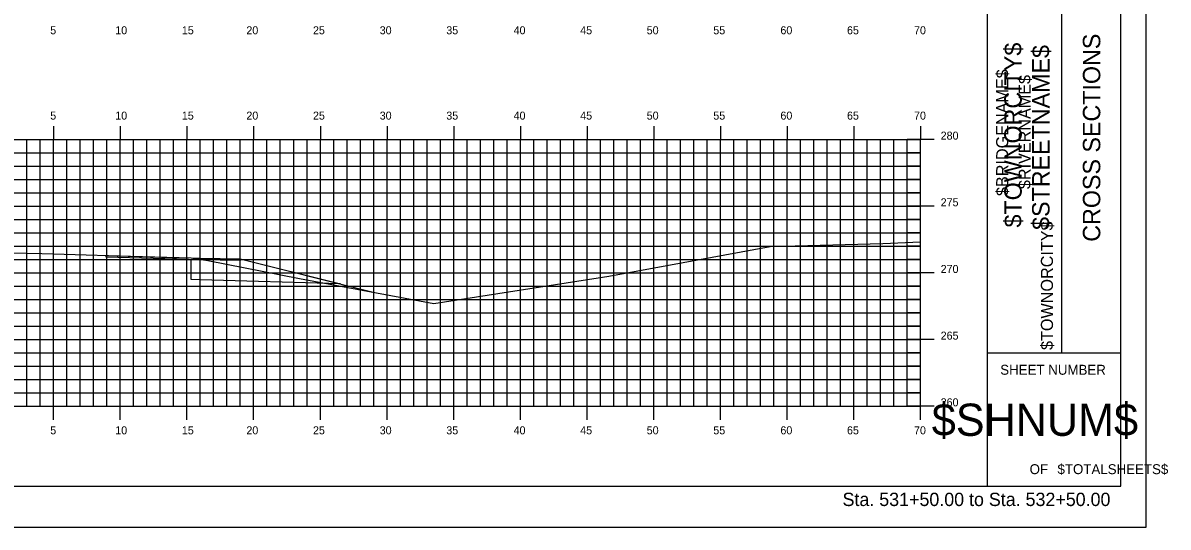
# Model space of a CAD drawing. Extents: x 1168600 to 1177589, y 610178 to 611246.
# Drawn here: x 1176838.4 to 1176924.2, y 610268.7 to 610306.6 of the extents above; entities that cross this region are included whole.
import ezdxf

# ---------------------------------------------------------------- set-up
doc = ezdxf.new("R2010")
doc.units = 0
for name, color, linetype in [('_Construction', 7, 'Continuous'), ('_Station Equation', 7, 'Continuous'), ('D_Roadway_Edge_TW', 7, 'Continuous'), ('D_Roadway_SubGrade', 7, 'Continuous'), ('D_Slope_Direction', 7, 'Continuous'), ('D_Text_Standard', 7, 'Continuous'), ('H_V ANNOTATION', 7, 'Continuous'), ('MAJOR', 7, 'Continuous'), ('MATCH LINES', 7, 'Continuous'), ('MINOR', 7, 'Continuous')]:
    doc.layers.add(name, color=color, linetype=linetype)

msp = doc.modelspace()

# ---------------------------------------------------------------- linework, layer by layer
at = {"layer": '_Construction'}
for p, q in [((1176910.655, 610271.804), (1176910.655, 610376.804)), ((1176920.655, 610271.804), (1176920.655, 610376.804)), ((1176916.246, 610281.804), (1176916.246, 610316.804)), ((1176910.655, 610281.804), (1176920.655, 610281.804)), ((1176760.655, 610271.801), (1176920.655, 610271.801))]:
    msp.add_line(p, q, dxfattribs=at)
msp.add_lwpolyline([(1176752.561, 610268.742), (1176922.561, 610268.742), (1176922.561, 610378.742), (1176752.561, 610378.742)], close=True, dxfattribs=at)
at = {"layer": '_Station Equation'}
msp.add_lwpolyline([(1176837.564, 610289.309), (1176839.769, 610289.258), (1176848.1, 610289.014), (1176849.945, 610288.956), (1176850.97, 610288.929), (1176851.322, 610288.87), (1176851.415, 610288.849), (1176852.211, 610288.745), (1176859.099, 610287.386), (1176869.173, 610285.511), (1176882.278, 610287.566), (1176894.366, 610289.791), (1176902.811, 610290.009), (1176905.654, 610290.135)], dxfattribs=at)
at = {"layer": 'D_Roadway_Edge_TW'}
msp.add_lwpolyline([(1176844.604, 610289.116), (1176850.97, 610288.929), (1176851.655, 610288.909), (1176851.655, 610288.784), (1176844.604, 610288.991), (1176844.604, 610289.116)], dxfattribs=at)
msp.add_lwpolyline([(1176844.604, 610289.116), (1176850.97, 610288.929), (1176851.655, 610288.909), (1176851.655, 610288.784), (1176844.604, 610288.991), (1176844.604, 610289.116)], dxfattribs=at)
msp.add_lwpolyline([(1176844.604, 610289.116), (1176850.97, 610288.929), (1176851.655, 610288.909), (1176854.653, 610288.851), (1176854.653, 610288.726), (1176851.655, 610288.784), (1176844.604, 610288.991)], close=True, dxfattribs=at)
msp.add_lwpolyline([(1176844.604, 610289.116), (1176850.97, 610288.929), (1176851.655, 610288.909), (1176854.653, 610288.851), (1176854.653, 610288.726), (1176851.655, 610288.784), (1176844.604, 610288.991)], close=True, dxfattribs=at)
at = {"layer": 'D_Roadway_SubGrade'}
msp.add_lwpolyline([(1176851.655, 610288.909), (1176854.653, 610288.851), (1176862.157, 610286.975), (1176851.655, 610287.284), (1176850.97, 610287.304), (1176850.97, 610288.804), (1176851.655, 610288.784)], close=True, dxfattribs=at)
msp.add_lwpolyline([(1176851.655, 610288.909), (1176854.653, 610288.851), (1176862.157, 610286.975), (1176851.655, 610287.284), (1176850.97, 610287.304), (1176850.97, 610288.804), (1176851.655, 610288.784)], close=True, dxfattribs=at)
at = {"layer": 'D_Slope_Direction'}
msp.add_lwpolyline([(1176851.655, 610288.909), (1176854.653, 610288.851)], dxfattribs=at)
msp.add_lwpolyline([(1176851.655, 610288.909), (1176854.653, 610288.851)], dxfattribs=at)
at = {"layer": 'D_Text_Standard'}
msp.add_lwpolyline([(1176844.604, 610289.116), (1176849.572, 610288.97), (1176850.97, 610288.929), (1176851.491, 610288.914), (1176851.655, 610288.909), (1176854.11, 610288.861), (1176854.653, 610288.851), (1176864.024, 610286.508), (1176864.624, 610286.358)], dxfattribs=at)
at = {"layer": 'MAJOR'}
for p, q in [((1176840.654, 610298.803), (1176840.654, 610297.801)), ((1176845.654, 610298.803), (1176845.654, 610297.801)), ((1176850.654, 610298.803), (1176850.654, 610297.801)), ((1176855.654, 610298.803), (1176855.654, 610297.801)), ((1176860.654, 610298.803), (1176860.654, 610297.801)), ((1176865.654, 610298.803), (1176865.654, 610297.801)), ((1176870.654, 610298.803), (1176870.654, 610297.801)), ((1176875.654, 610298.803), (1176875.654, 610297.801)), ((1176880.654, 610298.803), (1176880.654, 610297.801)), ((1176885.654, 610298.803), (1176885.654, 610297.801)), ((1176890.654, 610298.803), (1176890.654, 610297.801)), ((1176895.654, 610298.803), (1176895.654, 610297.801)), ((1176900.654, 610298.803), (1176900.654, 610297.801)), ((1176905.654, 610298.803), (1176905.654, 610297.801)), ((1176765.654, 610297.801), (1176905.654, 610297.801)), ((1176765.654, 610297.801), (1176905.654, 610297.801)), ((1176840.654, 610277.801), (1176840.654, 610297.801)), ((1176845.654, 610277.801), (1176845.654, 610297.801)), ((1176850.654, 610277.801), (1176850.654, 610297.801)), ((1176855.654, 610277.801), (1176855.654, 610297.801)), ((1176860.654, 610277.801), (1176860.654, 610297.801)), ((1176865.654, 610277.801), (1176865.654, 610297.801)), ((1176870.654, 610277.801), (1176870.654, 610297.801)), ((1176875.654, 610277.801), (1176875.654, 610297.801)), ((1176880.654, 610277.801), (1176880.654, 610297.801)), ((1176885.654, 610277.801), (1176885.654, 610297.801)), ((1176890.654, 610277.801), (1176890.654, 610297.801)), ((1176895.654, 610277.801), (1176895.654, 610297.801)), ((1176900.654, 610277.801), (1176900.654, 610297.801)), ((1176906.656, 610297.801), (1176904.652, 610297.801)), ((1176905.654, 610277.801), (1176905.654, 610297.801)), ((1176905.654, 610277.801), (1176905.654, 610297.801)), ((1176765.654, 610292.801), (1176905.654, 610292.801)), ((1176906.656, 610292.801), (1176904.652, 610292.801)), ((1176765.654, 610287.801), (1176905.654, 610287.801)), ((1176906.656, 610287.801), (1176904.652, 610287.801)), ((1176765.654, 610282.801), (1176905.654, 610282.801)), ((1176906.656, 610282.801), (1176904.652, 610282.801)), ((1176765.654, 610277.801), (1176905.654, 610277.801)), ((1176765.654, 610277.801), (1176905.654, 610277.801)), ((1176840.654, 610276.799), (1176840.654, 610277.801)), ((1176845.654, 610276.799), (1176845.654, 610277.801)), ((1176850.654, 610276.799), (1176850.654, 610277.801)), ((1176855.654, 610276.799), (1176855.654, 610277.801)), ((1176860.654, 610276.799), (1176860.654, 610277.801)), ((1176865.654, 610276.799), (1176865.654, 610277.801)), ((1176870.654, 610276.799), (1176870.654, 610277.801)), ((1176875.654, 610276.799), (1176875.654, 610277.801)), ((1176880.654, 610276.799), (1176880.654, 610277.801)), ((1176885.654, 610276.799), (1176885.654, 610277.801)), ((1176890.654, 610276.799), (1176890.654, 610277.801)), ((1176895.654, 610276.799), (1176895.654, 610277.801)), ((1176900.654, 610276.799), (1176900.654, 610277.801)), ((1176906.656, 610277.801), (1176904.652, 610277.801)), ((1176905.654, 610276.799), (1176905.654, 610277.801))]:
    msp.add_line(p, q, dxfattribs=at)
at = {"layer": 'MATCH LINES'}
msp.add_lwpolyline([(1176851.655, 610288.909), (1176851.655, 610288.784)], dxfattribs=at)
msp.add_lwpolyline([(1176851.655, 610288.909), (1176851.655, 610288.784)], dxfattribs=at)
at = {"layer": 'MINOR'}
for p, q in [((1176838.654, 610277.801), (1176838.654, 610297.801)), ((1176839.654, 610277.801), (1176839.654, 610297.801)), ((1176841.654, 610277.801), (1176841.654, 610297.801)), ((1176842.654, 610277.801), (1176842.654, 610297.801)), ((1176843.654, 610277.801), (1176843.654, 610297.801)), ((1176844.654, 610277.801), (1176844.654, 610297.801)), ((1176846.654, 610277.801), (1176846.654, 610297.801)), ((1176847.654, 610277.801), (1176847.654, 610297.801)), ((1176848.654, 610277.801), (1176848.654, 610297.801)), ((1176849.654, 610277.801), (1176849.654, 610297.801)), ((1176851.654, 610277.801), (1176851.654, 610297.801)), ((1176852.654, 610277.801), (1176852.654, 610297.801)), ((1176853.654, 610277.801), (1176853.654, 610297.801)), ((1176854.654, 610277.801), (1176854.654, 610297.801)), ((1176856.654, 610277.801), (1176856.654, 610297.801)), ((1176857.654, 610277.801), (1176857.654, 610297.801)), ((1176858.654, 610277.801), (1176858.654, 610297.801)), ((1176859.654, 610277.801), (1176859.654, 610297.801)), ((1176861.654, 610277.801), (1176861.654, 610297.801)), ((1176862.654, 610277.801), (1176862.654, 610297.801)), ((1176863.654, 610277.801), (1176863.654, 610297.801)), ((1176864.654, 610277.801), (1176864.654, 610297.801)), ((1176866.654, 610277.801), (1176866.654, 610297.801)), ((1176867.654, 610277.801), (1176867.654, 610297.801)), ((1176868.654, 610277.801), (1176868.654, 610297.801)), ((1176869.654, 610277.801), (1176869.654, 610297.801)), ((1176871.654, 610277.801), (1176871.654, 610297.801)), ((1176872.654, 610277.801), (1176872.654, 610297.801)), ((1176873.654, 610277.801), (1176873.654, 610297.801)), ((1176874.654, 610277.801), (1176874.654, 610297.801)), ((1176876.654, 610277.801), (1176876.654, 610297.801)), ((1176877.654, 610277.801), (1176877.654, 610297.801)), ((1176878.654, 610277.801), (1176878.654, 610297.801)), ((1176879.654, 610277.801), (1176879.654, 610297.801)), ((1176881.654, 610277.801), (1176881.654, 610297.801)), ((1176882.654, 610277.801), (1176882.654, 610297.801)), ((1176883.654, 610277.801), (1176883.654, 610297.801)), ((1176884.654, 610277.801), (1176884.654, 610297.801)), ((1176886.654, 610277.801), (1176886.654, 610297.801)), ((1176887.654, 610277.801), (1176887.654, 610297.801)), ((1176888.654, 610277.801), (1176888.654, 610297.801)), ((1176889.654, 610277.801), (1176889.654, 610297.801)), ((1176891.654, 610277.801), (1176891.654, 610297.801)), ((1176892.654, 610277.801), (1176892.654, 610297.801)), ((1176893.654, 610277.801), (1176893.654, 610297.801)), ((1176894.654, 610277.801), (1176894.654, 610297.801)), ((1176896.654, 610277.801), (1176896.654, 610297.801)), ((1176897.654, 610277.801), (1176897.654, 610297.801)), ((1176898.654, 610277.801), (1176898.654, 610297.801)), ((1176899.654, 610277.801), (1176899.654, 610297.801)), ((1176901.654, 610277.801), (1176901.654, 610297.801)), ((1176902.654, 610277.801), (1176902.654, 610297.801)), ((1176903.654, 610277.801), (1176903.654, 610297.801)), ((1176904.654, 610277.801), (1176904.654, 610297.801)), ((1176765.654, 610296.801), (1176905.654, 610296.801)), ((1176905.654, 610296.801), (1176904.652, 610296.801)), ((1176765.654, 610295.801), (1176905.654, 610295.801)), ((1176905.654, 610295.801), (1176904.652, 610295.801)), ((1176765.654, 610294.801), (1176905.654, 610294.801)), ((1176905.654, 610294.801), (1176904.652, 610294.801)), ((1176765.654, 610293.801), (1176905.654, 610293.801)), ((1176905.654, 610293.801), (1176904.652, 610293.801)), ((1176765.654, 610291.801), (1176905.654, 610291.801)), ((1176905.654, 610291.801), (1176904.652, 610291.801)), ((1176765.654, 610290.801), (1176905.654, 610290.801)), ((1176905.654, 610290.801), (1176904.652, 610290.801)), ((1176765.654, 610289.801), (1176905.654, 610289.801)), ((1176905.654, 610289.801), (1176904.652, 610289.801)), ((1176765.654, 610288.801), (1176905.654, 610288.801)), ((1176905.654, 610288.801), (1176904.652, 610288.801)), ((1176765.654, 610286.801), (1176905.654, 610286.801)), ((1176905.654, 610286.801), (1176904.652, 610286.801)), ((1176765.654, 610285.801), (1176905.654, 610285.801)), ((1176905.654, 610285.801), (1176904.652, 610285.801)), ((1176765.654, 610284.801), (1176905.654, 610284.801)), ((1176905.654, 610284.801), (1176904.652, 610284.801)), ((1176765.654, 610283.801), (1176905.654, 610283.801)), ((1176905.654, 610283.801), (1176904.652, 610283.801)), ((1176765.654, 610281.801), (1176905.654, 610281.801)), ((1176905.654, 610281.801), (1176904.652, 610281.801)), ((1176765.654, 610280.801), (1176905.654, 610280.801)), ((1176905.654, 610280.801), (1176904.652, 610280.801)), ((1176765.654, 610279.801), (1176905.654, 610279.801)), ((1176905.654, 610279.801), (1176904.652, 610279.801)), ((1176765.654, 610278.801), (1176905.654, 610278.801)), ((1176905.654, 610278.801), (1176904.652, 610278.801))]:
    msp.add_line(p, q, dxfattribs=at)

# ---------------------------------------------------------------- texts
at = {"layer": '_Construction'}
for s, height, rotation, p in [('CROSS SECTIONS', 1.30428, 90, (1176919.119, 610290.143)), ('$TOWNORCITY$', 1.30428, 90, (1176913.227, 610291.212)), ('$STREETNAME$', 1.30428, 90, (1176915.314, 610291.032)), ('$BRIDGENAME$', 0.90716, 90, (1176912.221, 610293.572)), ('$RIVERNAME$', 0.90716, 90, (1176913.898, 610294.087)), ('$TOWNORCITY$', 0.90716, 90, (1176915.575, 610282.025)), ('SHEET NUMBER', 0.74527, 360, (1176911.62, 610280.168)), ('$SHNUM$', 2.4194, 360, (1176906.488, 610275.584)), ('OF', 0.7453, 360, (1176913.822, 610272.714)), ('$TOTALSHEETS$', 0.74527, 360, (1176915.911, 610272.714))]:
    msp.add_text(s, height=height, rotation=rotation, dxfattribs=at).set_placement(p)
at = {"layer": 'H_V ANNOTATION'}
for s, height, p in [('5', 0.6, (1176840.406, 610305.701)), ('10', 0.6, (1176845.28, 610305.701)), ('15', 0.6, (1176850.272, 610305.701)), ('20', 0.6, (1176855.108, 610305.701)), ('25', 0.6, (1176860.1, 610305.701)), ('30', 0.6, (1176865.103, 610305.701)), ('35', 0.6, (1176870.095, 610305.701)), ('40', 0.6, (1176875.141, 610305.701)), ('45', 0.6, (1176880.133, 610305.701)), ('50', 0.6, (1176885.119, 610305.701)), ('55', 0.6, (1176890.111, 610305.701)), ('60', 0.6, (1176895.141, 610305.701)), ('65', 0.6, (1176900.133, 610305.701)), ('70', 0.6, (1176905.157, 610305.701)), ('5', 0.6, (1176840.406, 610299.301)), ('10', 0.6, (1176845.28, 610299.301)), ('15', 0.6, (1176850.272, 610299.301)), ('20', 0.6, (1176855.108, 610299.301)), ('25', 0.6, (1176860.1, 610299.301)), ('30', 0.6, (1176865.103, 610299.301)), ('35', 0.6, (1176870.095, 610299.301)), ('40', 0.6, (1176875.141, 610299.301)), ('45', 0.6, (1176880.133, 610299.301)), ('50', 0.6, (1176885.119, 610299.301)), ('55', 0.6, (1176890.111, 610299.301)), ('60', 0.6, (1176895.141, 610299.301)), ('65', 0.6, (1176900.133, 610299.301)), ('70', 0.6, (1176905.157, 610299.301)), ('280', 0.6, (1176907.154, 610297.801)), ('275', 0.6, (1176907.154, 610292.801)), ('270', 0.6, (1176907.154, 610287.801)), ('265', 0.6, (1176907.154, 610282.801)), ('260', 0.6, (1176907.154, 610277.801)), ('5', 0.6, (1176840.406, 610275.701)), ('10', 0.6, (1176845.28, 610275.701)), ('15', 0.6, (1176850.272, 610275.701)), ('20', 0.6, (1176855.108, 610275.701)), ('25', 0.6, (1176860.1, 610275.701)), ('30', 0.6, (1176865.103, 610275.701)), ('35', 0.6, (1176870.095, 610275.701)), ('40', 0.6, (1176875.141, 610275.701)), ('45', 0.6, (1176880.133, 610275.701)), ('50', 0.6, (1176885.119, 610275.701)), ('55', 0.6, (1176890.111, 610275.701)), ('60', 0.6, (1176895.141, 610275.701)), ('65', 0.6, (1176900.133, 610275.701)), ('70', 0.6, (1176905.157, 610275.701)), ('Sta. 531+50.00 to Sta. 532+50.00', 1.0002, (1176899.8, 610270.321))]:
    msp.add_text(s, height=height, dxfattribs=at).set_placement(p)

doc.saveas('drawing.dxf')
